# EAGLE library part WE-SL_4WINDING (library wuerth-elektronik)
SMD Common-Mode Choke for signal line WE-SL For distortion-free removal of noise from transmitted electrical signals -- Current compensated choke for data and signal lines -- USB/CAN/ISDN-Bus -- Power supply systems -- Control lines -- LAN, PBX, cable TV, CD-ROM, 8mm video, etc.
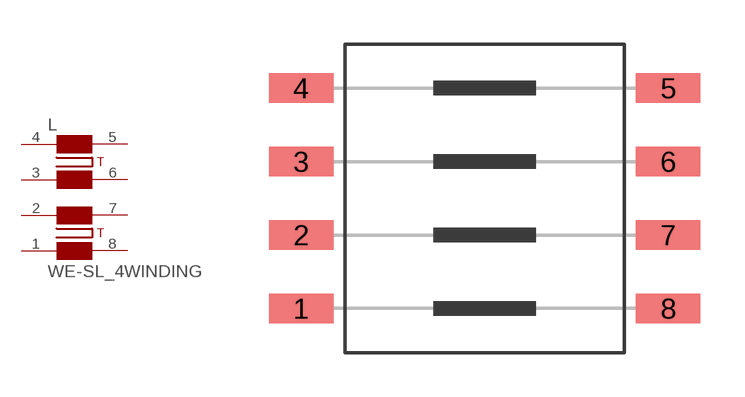
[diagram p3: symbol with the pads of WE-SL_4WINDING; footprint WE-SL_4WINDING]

Designator prefix L

## WE-SL_4WINDING  [WE-SL_4WINDING]
1  7  pas
2  5  pas
3  3  pas
4  1  pas
5  2  pas
6  4  pas
7  6  pas
8  8  pas

## Footprint WE-SL_4WINDING (pad centres in mm)
SMD Common-Mode Choke
smd 2.2 x 1: 1 -6.25,-3.75; 2 -6.25,-1.25; 3 -6.25,1.25; 4 -6.25,3.75; 5 6.25,3.75; 6 6.25,1.25; 7 6.25,-1.25; 8 6.25,-3.75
